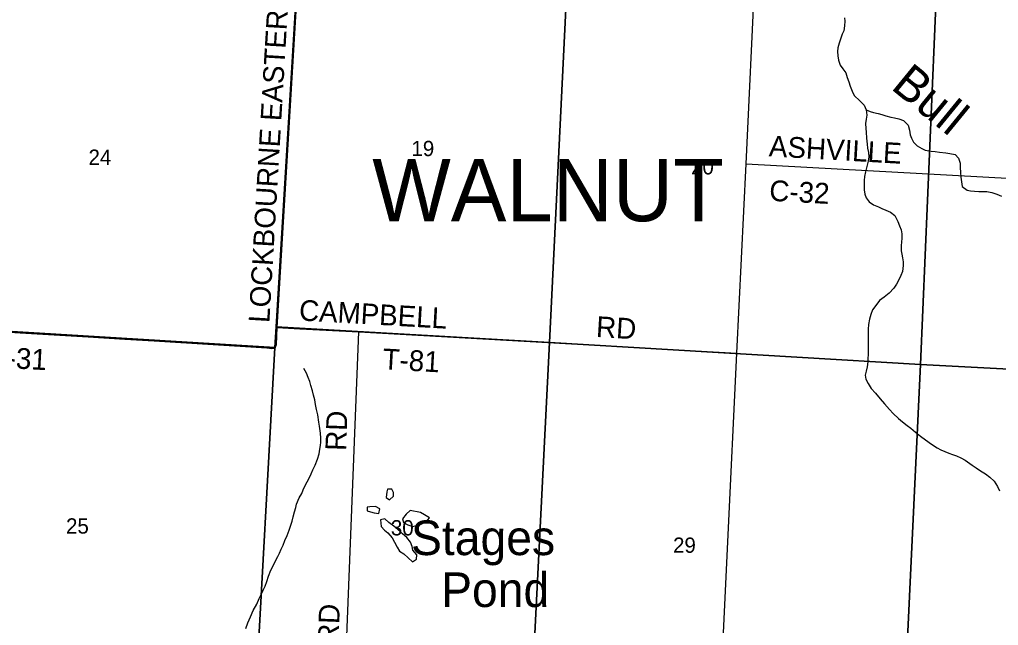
# Model space of a CAD drawing. Extents: x 1643459 to 2064572, y 425441 to 780708.
# Drawn here: x 1839200 to 1853344, y 609399 to 618149 of the extents above; entities that cross this region are included whole.
import ezdxf

# ---------------------------------------------------------------- set-up
doc = ezdxf.new("R2010")
doc.units = 0
for name, color, linetype in [('GM_X_Adjacent_County', 7, 'Continuous'), ('GM_X_Adjacent_County_Text', 7, 'Continuous'), ('GM_X_County_Road', 7, 'Continuous'), ('GM_X_Interchange_Ramps', 7, 'Continuous'), ('GM_X_Major_River', 7, 'Continuous'), ('GM_X_Major_River_Text', 7, 'Continuous'), ('GM_X_Minor_Lake', 7, 'Continuous'), ('GM_X_Section_Text', 7, 'Continuous'), ('GM_X_State_Route', 7, 'Continuous'), ('GM_X_Township_Subdivision_Text', 7, 'Continuous'), ('GM_X_US_Route', 7, 'Continuous')]:
    doc.layers.add(name, color=color, linetype=linetype)

msp = doc.modelspace()

# ---------------------------------------------------------------- linework, layer by layer
at = {"layer": 'GM_X_Major_River_Text'}
for points in [[(1841145, 613509), (1842774, 613409), (1842843, 613401), (1842878, 613404), (1842899, 613420), (1842912, 613457), (1842923, 613704), (1843254, 619240)], [(1837533, 613820), (1837555, 613770), (1837586, 613742), (1837605, 613728), (1837829, 613711), (1838598, 613663), (1839207, 613626)], [(1842923, 613704), (1843250, 613681), (1844100, 613639)], [(1839207, 613626), (1840191, 613565), (1840723, 613535), (1841145, 613509)], [(1843884, 608148), (1844100, 613639)], [(1844100, 613639), (1849566, 613329)]]:
    msp.add_lwpolyline(points, dxfattribs=at)
at = {"layer": 'GM_X_Minor_Lake'}
for points in [[(1849303, 607884), (1849566, 613329), (1849697, 616067), (1849830, 618825), (1849917, 620622), (1849894, 620912), (1849881, 621026), (1849866, 621149), (1849835, 621322)], [(1849697, 616067), (1857852, 615618), (1858903, 615558)]]:
    msp.add_lwpolyline(points, dxfattribs=at)
at = {"layer": 'GM_X_State_Route'}
for points in [[(1843247, 619225), (1847128, 618998), (1846856, 613483), (1842907, 613710), (1843213, 618737)], [(1843213, 618737), (1842907, 613710), (1842889, 613414), (1837502, 613740), (1837858, 619041)], [(1847128, 618998), (1852455, 618700), (1852218, 613168), (1846856, 613483)], [(1852455, 618700), (1858030, 618392), (1857717, 612877), (1852218, 613168)], [(1842889, 613414), (1842604, 608253), (1842595, 608085), (1837195, 608395), (1837502, 613740)], [(1842907, 613710), (1846856, 613483), (1846583, 608042), (1842604, 608253), (1842889, 613414)], [(1846856, 613483), (1852218, 613168), (1851962, 607792), (1846583, 608042)], [(1852218, 613168), (1857717, 612877), (1857425, 607464), (1851962, 607792)]]:
    msp.add_lwpolyline(points, close=True, dxfattribs=at)
at = {"layer": 'GM_X_Township_Subdivision_Text'}
for points in [[(1844221, 611108), (1844221, 611055), (1844271, 611039), (1844323, 611025), (1844390, 611015), (1844408, 611083), (1844344, 611115), (1844262, 611110)], [(1844262, 611110), (1844221, 611108)], [(1844843, 611061), (1844785, 611005), (1844732, 610937), (1844748, 610885), (1844810, 610850), (1844882, 610830), (1844949, 610846), (1845005, 610861), (1845077, 610893), (1845124, 610953), (1845052, 610998), (1844992, 611029)], [(1844992, 611029), (1844843, 611061)], [(1844702, 610758), (1844607, 610831), (1844537, 610887), (1844480, 610940), (1844417, 610924)], [(1844417, 610924), (1844423, 610826), (1844471, 610775), (1844523, 610735), (1844585, 610662), (1844618, 610600), (1844656, 610530), (1844692, 610473), (1844754, 610433), (1844814, 610376), (1844876, 610316), (1844938, 610354), (1844941, 610420), (1844883, 610485), (1844875, 610539), (1844851, 610601), (1844797, 610670), (1844735, 610724), (1844702, 610758)]]:
    msp.add_lwpolyline(points, dxfattribs=at)
at = {"layer": 'GM_X_US_Route'}
for points in [[(1851120, 618175), (1851125, 618125), (1851121, 618059), (1851109, 617988), (1851086, 617938), (1851060, 617868), (1851042, 617808), (1851023, 617740), (1851021, 617688), (1851025, 617626), (1851033, 617563), (1851056, 617493), (1851096, 617437), (1851138, 617378), (1851160, 617314), (1851182, 617252), (1851200, 617189), (1851229, 617113), (1851261, 617055), (1851343, 616978), (1851405, 616915), (1851433, 616847), (1851444, 616771), (1851432, 616713), (1851422, 616648), (1851426, 616576), (1851431, 616522), (1851437, 616438), (1851445, 616349), (1851454, 616291), (1851466, 616231), (1851472, 616168), (1851462, 616102), (1851443, 616028), (1851421, 615950), (1851408, 615882), (1851404, 615827), (1851402, 615757), (1851404, 615691), (1851413, 615629), (1851433, 615576), (1851475, 615516), (1851541, 615474), (1851609, 615443), (1851659, 615421), (1851719, 615399), (1851783, 615370), (1851847, 615322), (1851891, 615233), (1851915, 615169), (1851939, 615115), (1851946, 615054), (1851946, 614992), (1851944, 614934), (1851940, 614884), (1851941, 614811), (1851947, 614759), (1851959, 614707)], [(1851433, 616847), (1851489, 616821), (1851539, 616806), (1851607, 616792), (1851659, 616776), (1851717, 616761), (1851787, 616741), (1851840, 616729), (1851904, 616715), (1851970, 616690), (1852038, 616624), (1852059, 616553), (1852071, 616485), (1852087, 616435), (1852117, 616380), (1852169, 616328), (1852235, 616286), (1852287, 616263), (1852373, 616247), (1852429, 616243), (1852491, 616236), (1852582, 616226), (1852642, 616216), (1852718, 616199), (1852768, 616149), (1852790, 616074), (1852791, 616014), (1852797, 615940), (1852801, 615872), (1852809, 615807), (1852818, 615739), (1852890, 615687), (1852940, 615678), (1852997, 615670), (1853059, 615664), (1853109, 615666), (1853175, 615665), (1853251, 615651), (1853319, 615626), (1853388, 615600)], [(1851959, 614707), (1851969, 614651), (1851968, 614597), (1851956, 614512), (1851936, 614452), (1851911, 614400), (1851873, 614330), (1851831, 614268), (1851764, 614198), (1851694, 614142), (1851625, 614094), (1851571, 614022), (1851526, 613956), (1851500, 613888), (1851483, 613824), (1851467, 613744), (1851461, 613679), (1851460, 613561), (1851462, 613511), (1851464, 613425), (1851463, 613370), (1851461, 613312), (1851457, 613256), (1851455, 613206), (1851448, 613136), (1851434, 613071), (1851420, 613013), (1851427, 612957), (1851461, 612891), (1851503, 612822), (1851567, 612752), (1851637, 612673), (1851699, 612601), (1851769, 612518), (1851821, 612462), (1851900, 612389), (1851960, 612340), (1852026, 612288), (1852080, 612246), (1852144, 612191), (1852218, 612131), (1852344, 612040), (1852408, 611997), (1852460, 611965), (1852512, 611937), (1852569, 611910), (1852625, 611888), (1852681, 611870), (1852737, 611847), (1852803, 611819), (1852865, 611785), (1852965, 611716), (1853023, 611677), (1853087, 611633), (1853157, 611587), (1853221, 611542), (1853283, 611482), (1853329, 611405), (1853359, 611343)], [(1843504, 611799), (1843527, 611879), (1843541, 611944), (1843547, 611998), (1843551, 612048), (1843552, 612104), (1843548, 612178), (1843534, 612277), (1843523, 612333), (1843509, 612441), (1843491, 612520), (1843478, 612592), (1843466, 612658), (1843448, 612727), (1843434, 612787), (1843411, 612863), (1843395, 612922), (1843371, 612978), (1843345, 613042), (1843309, 613111)], [(1842472, 609357), (1842500, 609439), (1842537, 609523), (1842577, 609613), (1842628, 609708), (1842664, 609786), (1842695, 609856), (1842719, 609910), (1842749, 609968), (1842772, 610032), (1842798, 610112), (1842833, 610196), (1842869, 610270), (1842902, 610341), (1842930, 610395), (1842958, 610445), (1842981, 610499), (1843007, 610557), (1843035, 610625), (1843066, 610699), (1843096, 610775), (1843119, 610845), (1843137, 610906), (1843153, 610968), (1843172, 611040), (1843190, 611100), (1843202, 611150), (1843241, 611244), (1843277, 611304), (1843297, 611357), (1843326, 611419), (1843358, 611475), (1843391, 611537), (1843413, 611587), (1843439, 611645), (1843470, 611715), (1843504, 611799)], [(1844509, 611329), (1844495, 611249), (1844545, 611215), (1844601, 611265), (1844602, 611317), (1844580, 611369), (1844516, 611365)], [(1844516, 611365), (1844509, 611329)]]:
    msp.add_lwpolyline(points, dxfattribs=at)

# ---------------------------------------------------------------- texts
at = {"layer": 'GM_X_Adjacent_County'}
for s, p in [('19', (1844863, 616177)), ('24', (1840197, 616051)), ('20', (1848903, 615913)), ('25', (1839872, 610725)), ('30', (1844566, 610699)), ('29', (1848643, 610448))]:
    msp.add_text(s, height=221, rotation=0, dxfattribs=at).set_placement(p)
at = {"layer": 'GM_X_Adjacent_County_Text'}
msp.add_text('WALNUT', height=900, rotation=0, dxfattribs=at).set_placement((1844296, 615237))
at = {"layer": 'GM_X_County_Road'}
for s, p in [('Stages', (1844857, 610415)), ('Pond', (1845292, 609665))]:
    msp.add_text(s, height=500, dxfattribs=at).set_placement(p)
at = {"layer": 'GM_X_Interchange_Ramps'}
msp.add_text('Bull', height=500, rotation=320.6879, dxfattribs=at).set_placement((1851775, 617158))
at = {"layer": 'GM_X_Major_River'}
for s, rotation, p in [('LOCKBOURNE EASTERN RD', 86.6183, (1842809, 613763)), ('CAMPBELL', 356.8061, (1843233, 613804)), ('RD', 356.5467, (1847524, 613566)), ('T-31', 356.8199, (1838763, 613131)), ('T-81', 356.8193, (1844439, 613100)), ('RD', 88.0242, (1843918, 611917)), ('WARD', 87.7546, (1843782, 608481))]:
    msp.add_text(s, height=300, rotation=rotation, dxfattribs=at).set_placement(p)
at = {"layer": 'GM_X_Section_Text'}
for s, rotation, p in [('ASHVILLE', 356.7578, (1850022, 616175)), ('C-32', 356.897, (1850027, 615533))]:
    msp.add_text(s, height=300, rotation=rotation, dxfattribs=at).set_placement(p)

doc.saveas('drawing.dxf')
